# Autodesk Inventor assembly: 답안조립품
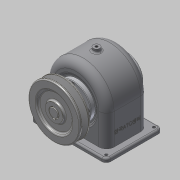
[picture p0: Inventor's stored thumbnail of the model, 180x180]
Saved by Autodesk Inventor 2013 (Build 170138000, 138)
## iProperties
Created: 2016-01
Part Number: 답안조립품
Document SubType Name: Assembly
Designer: dgall
Author: dgall
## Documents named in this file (16)
- C:\Users\dgall\Desktop\460105V1015\답안조립품.iam
- C:\Users\dgall\Desktop\460105V1015\본체.ipt
- C:\Users\dgall\Desktop\460105V1015\V-벨트풀리.ipt
- C:\Users\dgall\Desktop\460105V1015\뒤커버.ipt
- C:\Users\dgall\Desktop\460105V1015\멈춤나사 - M4x10.ipt
- C:\Users\dgall\Desktop\460105V1015\베어링 6203.ipt
- C:\Users\dgall\Desktop\460105V1015\볼트 M3 x 8.ipt
- C:\Users\dgall\Desktop\460105V1015\볼트 M3 x 10.ipt
- C:\Users\dgall\Desktop\460105V1015\부시1.ipt
- C:\Users\dgall\Desktop\460105V1015\부시2.ipt
- C:\Users\dgall\Desktop\460105V1015\스퍼기어.ipt
- C:\Users\dgall\Desktop\460105V1015\앞커버.ipt
- C:\Users\dgall\Desktop\460105V1015\오일씰 28 40 8.ipt
- C:\Users\dgall\Desktop\460105V1015\축.ipt
- C:\Users\dgall\Desktop\460105V1015\키 - 5 x 5 x 18.ipt
- C:\Users\dgall\Desktop\460105V1015\키 - 6 x 6 x 22.ipt
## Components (9 placed, 3 different names)
1. V-벨트풀리:1
2. ISO 4762 M3 x 10:1
3. ISO 4762 M3 x 10:2
4. ISO 4762 M3 x 10:3
5. ISO 4762 M3 x 10:4
6. ISO 4762 M3 x 8:1
7. ISO 4762 M3 x 8:2
8. ISO 4762 M3 x 8:3
9. ISO 4762 M3 x 8:4
